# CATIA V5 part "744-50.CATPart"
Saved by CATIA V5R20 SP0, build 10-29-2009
Part number: 744-50
Revision: TUTTO
Definition: NON CONOSCIUTO
Nomenclature: 744-50
Source: Unknown
Bounding box of the stored display mesh (mm): x -40 to 40, y -40.5 to 40, z -47 to 50
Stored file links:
  C:\Users\Utente\Desktop\IO LAVORO\3D X SITO CF\X SITO\744\744-50.CATPart
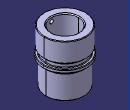
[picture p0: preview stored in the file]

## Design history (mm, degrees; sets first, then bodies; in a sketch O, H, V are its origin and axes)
Body1 "744-50 sol1" (main body)
  Solid1: solid without history
Body2 "IDV1M8_Ingrassatore-1"
  Solid2: solid without history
